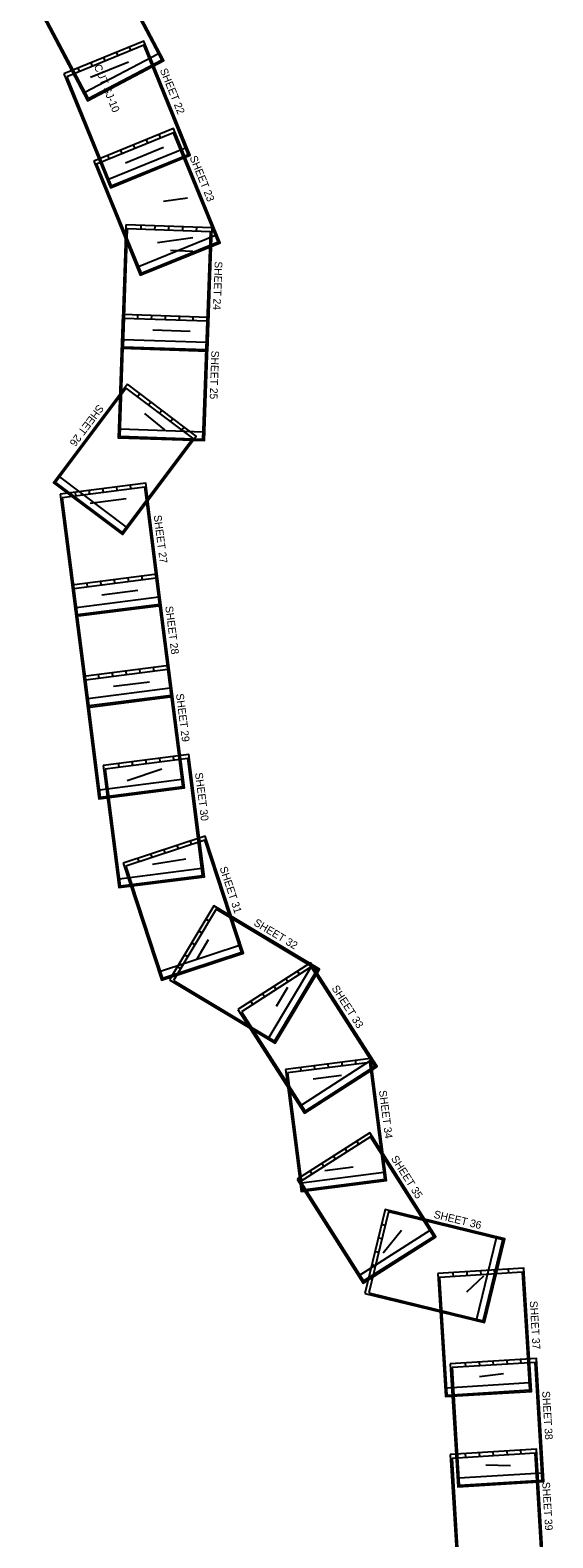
# Model space of a CAD drawing. Extents: x 518852 to 589310, y 1937169 to 2155394.
# Drawn here: x 536569 to 553550, y 2050636 to 2099579 of the extents above; entities that cross this region are included whole.
import ezdxf

# ---------------------------------------------------------------- set-up
doc = ezdxf.new("R2010")
doc.units = 0
doc.layers.add('Level 1', color=7, linetype='Continuous')
doc.layers.add('Level 58', color=7, linetype='Continuous')

msp = doc.modelspace()

# ---------------------------------------------------------------- linework, layer by layer
at = {"layer": 'Level 1'}
for p, q in [((537257, 2099523), (537301, 2099546)), ((540529, 2099214), (540573, 2099237)), ((537467, 2099125), (537511, 2099148)), ((537677, 2098727), (537721, 2098750)), ((540739, 2098815), (538351, 2097556)), ((539011, 2098578), (538963, 2098693)), ((539011, 2098578), (538963, 2098693)), ((539427, 2098747), (539380, 2098863)), ((539427, 2098747), (539380, 2098863)), ((539844, 2098917), (539797, 2099033)), ((539844, 2098917), (539797, 2099033)), ((540431, 2098670), (540477, 2098689)), ((540431, 2098670), (540477, 2098689)), ((537887, 2098329), (537931, 2098352)), ((538177, 2098238), (538130, 2098354)), ((538177, 2098238), (538130, 2098354)), ((538594, 2098408), (538547, 2098523)), ((538594, 2098408), (538547, 2098523)), ((540071, 2098152), (540048, 2098197)), ((540469, 2098362), (540446, 2098407)), ((540600, 2098254), (540647, 2098272)), ((540600, 2098254), (540647, 2098272)), ((538097, 2097931), (538141, 2097954)), ((539275, 2097733), (539252, 2097777)), ((539673, 2097943), (539650, 2097987)), ((540770, 2097837), (540817, 2097856)), ((540770, 2097837), (540817, 2097856)), ((537884, 2097632), (537930, 2097651)), ((537884, 2097632), (537930, 2097651)), ((538054, 2097216), (538100, 2097235)), ((538054, 2097216), (538100, 2097235)), ((538877, 2097523), (538854, 2097567)), ((540940, 2097420), (540986, 2097439)), ((540940, 2097420), (540986, 2097439)), ((538224, 2096799), (538270, 2096818)), ((538224, 2096799), (538270, 2096818)), ((541110, 2097003), (541156, 2097022)), ((541110, 2097003), (541156, 2097022)), ((538394, 2096382), (538440, 2096401)), ((538394, 2096382), (538440, 2096401)), ((541280, 2096587), (541326, 2096606)), ((541280, 2096587), (541326, 2096606)), ((538563, 2095966), (538610, 2095984)), ((538563, 2095966), (538610, 2095984)), ((541619, 2095753), (539119, 2094734)), ((541619, 2095753), (539119, 2094734)), ((539979, 2095738), (539931, 2095854)), ((540395, 2095908), (540348, 2096024)), ((540812, 2096078), (540765, 2096193)), ((541399, 2095831), (541445, 2095850)), ((541450, 2096170), (541496, 2096189)), ((541450, 2096170), (541496, 2096189)), ((538733, 2095549), (538779, 2095568)), ((538733, 2095549), (538779, 2095568)), ((539145, 2095398), (539098, 2095514)), ((539562, 2095568), (539515, 2095684)), ((541307, 2095329), (541288, 2095375)), ((541307, 2095329), (541288, 2095375)), ((541568, 2095414), (541615, 2095433)), ((538852, 2094793), (538898, 2094812)), ((538903, 2095132), (538949, 2095151)), ((538903, 2095132), (538949, 2095151)), ((540056, 2094819), (540038, 2094866)), ((540056, 2094819), (540038, 2094866)), ((540473, 2094989), (540454, 2095035)), ((540473, 2094989), (540454, 2095035)), ((540890, 2095159), (540871, 2095205)), ((540890, 2095159), (540871, 2095205)), ((541738, 2094997), (541785, 2095016)), ((539022, 2094376), (539068, 2094395)), ((539640, 2094649), (539621, 2094696)), ((539640, 2094649), (539621, 2094696)), ((541908, 2094581), (541954, 2094599)), ((539192, 2093959), (539238, 2093978)), ((542078, 2094164), (542124, 2094183)), ((539361, 2093543), (539408, 2093562)), ((542248, 2093747), (542294, 2093766)), ((542418, 2093330), (542464, 2093349)), ((539531, 2093126), (539578, 2093145)), ((542587, 2092914), (540087, 2091895)), ((540175, 2093112), (540180, 2093237)), ((540625, 2093096), (540630, 2093221)), ((541075, 2093081), (541079, 2093206)), ((541525, 2093065), (541529, 2093190)), ((541974, 2093050), (541979, 2093175)), ((539660, 2092679), (539710, 2092677)), ((539701, 2092709), (539747, 2092728)), ((541858, 2092319), (541839, 2092366)), ((542274, 2092489), (542256, 2092535)), ((542409, 2092584), (542459, 2092583)), ((539645, 2092229), (539695, 2092228)), ((539871, 2092293), (539917, 2092311)), ((540608, 2091810), (540589, 2091856)), ((541024, 2091980), (541005, 2092026)), ((541441, 2092150), (541422, 2092196)), ((542393, 2092135), (542443, 2092133)), ((539629, 2091780), (539679, 2091778)), ((542378, 2091685), (542428, 2091683)), ((539598, 2090880), (539648, 2090878)), ((539614, 2091330), (539664, 2091328)), ((542362, 2091235), (542412, 2091233)), ((539583, 2090430), (539633, 2090429)), ((542347, 2090785), (542397, 2090784)), ((539567, 2089981), (539617, 2089979)), ((540067, 2090205), (540071, 2090330)), ((540516, 2090190), (540521, 2090315)), ((540966, 2090174), (540970, 2090299)), ((541416, 2090159), (541420, 2090284)), ((541865, 2090143), (541870, 2090268)), ((542316, 2089886), (542366, 2089884)), ((542331, 2090336), (542381, 2090334)), ((539551, 2089773), (539601, 2089771)), ((542300, 2089436), (539602, 2089529)), ((542300, 2089678), (542350, 2089676)), ((539536, 2089323), (539586, 2089321)), ((540042, 2089239), (540044, 2089289)), ((540492, 2089223), (540493, 2089273)), ((540941, 2089208), (540943, 2089258)), ((541391, 2089192), (541393, 2089242)), ((541841, 2089177), (541843, 2089227)), ((542284, 2089228), (542334, 2089227)), ((539505, 2088424), (539555, 2088422)), ((539520, 2088873), (539570, 2088872)), ((542269, 2088779), (542319, 2088777)), ((539489, 2087974), (539539, 2087972)), ((542253, 2088329), (542303, 2088327)), ((539383, 2087625), (539423, 2087595)), ((539474, 2087524), (539524, 2087522)), ((540053, 2087684), (540128, 2087784)), ((540413, 2087414), (540488, 2087514)), ((542222, 2087429), (542272, 2087428)), ((542238, 2087879), (542288, 2087877)), ((539113, 2087265), (539153, 2087235)), ((539458, 2087074), (539508, 2087073)), ((540773, 2087144), (540848, 2087244)), ((541133, 2086874), (541208, 2086974)), ((542207, 2086980), (542257, 2086978)), ((538573, 2086545), (538613, 2086515)), ((538843, 2086905), (538883, 2086875)), ((542191, 2086530), (539493, 2086623)), ((541493, 2086604), (541568, 2086704)), ((538303, 2086185), (538343, 2086155)), ((539933, 2086333), (539935, 2086383)), ((540383, 2086317), (540385, 2086367)), ((540833, 2086302), (540834, 2086352)), ((541282, 2086286), (541284, 2086336)), ((541583, 2085974), (541623, 2085944)), ((541732, 2086271), (541734, 2086321)), ((538033, 2085825), (538073, 2085795)), ((541312, 2085614), (541352, 2085584)), ((539692, 2083455), (537532, 2085075)), ((537762, 2085465), (537802, 2085435)), ((541042, 2085254), (541082, 2085224)), ((537727, 2084585), (537757, 2084625)), ((538059, 2084458), (538043, 2084582)), ((538505, 2084515), (538489, 2084639)), ((538951, 2084572), (538936, 2084696)), ((539398, 2084629), (539382, 2084753)), ((539844, 2084686), (539828, 2084810)), ((540502, 2084534), (540542, 2084504)), ((540772, 2084894), (540812, 2084864)), ((538087, 2084315), (538117, 2084355)), ((538447, 2084045), (538477, 2084085)), ((540232, 2084174), (540272, 2084144)), ((540348, 2084296), (540397, 2084303)), ((537620, 2083948), (537669, 2083954)), ((538807, 2083775), (538837, 2083815)), ((539167, 2083505), (539197, 2083545)), ((539962, 2083814), (540002, 2083784)), ((540405, 2083850), (540454, 2083856)), ((537677, 2083502), (537726, 2083508)), ((537734, 2083055), (537783, 2083062)), ((540462, 2083404), (540511, 2083410)), ((537791, 2082609), (537840, 2082615)), ((540519, 2082957), (540568, 2082964)), ((537848, 2082162), (537897, 2082169)), ((540576, 2082511), (540625, 2082517)), ((540633, 2082065), (540682, 2082071)), ((537905, 2081716), (537954, 2081722)), ((538432, 2081503), (538417, 2081627)), ((538879, 2081560), (538863, 2081684)), ((539325, 2081617), (539309, 2081741)), ((539772, 2081674), (539756, 2081798)), ((540218, 2081731), (540202, 2081855)), ((540690, 2081618), (540739, 2081625)), ((537962, 2081270), (538012, 2081276)), ((540747, 2081172), (538069, 2080830)), ((540721, 2081342), (540771, 2081348)), ((537993, 2080993), (538043, 2080999)), ((538550, 2080614), (538543, 2080664)), ((538996, 2080671), (538990, 2080721)), ((539442, 2080728), (539436, 2080778)), ((539889, 2080785), (539883, 2080835)), ((540335, 2080842), (540329, 2080892)), ((540778, 2080895), (540828, 2080902)), ((538051, 2080547), (538100, 2080553)), ((538108, 2080100), (538157, 2080107)), ((540835, 2080449), (540885, 2080455)), ((538165, 2079654), (538214, 2079660)), ((540892, 2080003), (540942, 2080009)), ((538222, 2079208), (538271, 2079214)), ((540949, 2079556), (540999, 2079562)), ((541006, 2079110), (541056, 2079116)), ((538279, 2078761), (538328, 2078768)), ((538809, 2078536), (538794, 2078660)), ((539256, 2078593), (539240, 2078717)), ((539702, 2078650), (539686, 2078774)), ((540148, 2078707), (540133, 2078831)), ((540595, 2078764), (540579, 2078888)), ((541064, 2078663), (541113, 2078670)), ((538336, 2078315), (538385, 2078321)), ((541121, 2078217), (538442, 2077875)), ((541098, 2078374), (541148, 2078381)), ((538370, 2078026), (538420, 2078032)), ((538924, 2077659), (538917, 2077709)), ((539370, 2077716), (539364, 2077766)), ((539816, 2077773), (539810, 2077823)), ((540263, 2077830), (540256, 2077880)), ((540709, 2077887), (540703, 2077937)), ((541155, 2077928), (541205, 2077934)), ((538427, 2077580), (538477, 2077586)), ((541212, 2077482), (541262, 2077488)), ((538484, 2077133), (538534, 2077140)), ((538542, 2076687), (538591, 2076693)), ((541269, 2077035), (541319, 2077042)), ((538599, 2076240), (538648, 2076247)), ((541326, 2076589), (541376, 2076595)), ((538656, 2075794), (538705, 2075800)), ((539456, 2075651), (539440, 2075775)), ((539902, 2075708), (539887, 2075832)), ((540349, 2075765), (540333, 2075889)), ((540795, 2075822), (540779, 2075946)), ((541242, 2075879), (541226, 2076003)), ((541383, 2076143), (541433, 2076149)), ((541440, 2075696), (541490, 2075703)), ((538713, 2075348), (538762, 2075354)), ((541497, 2075250), (538819, 2074908)), ((541745, 2075490), (541795, 2075496)), ((539017, 2075141), (539067, 2075147)), ((539074, 2074695), (539124, 2074701)), ((539300, 2074692), (539294, 2074742)), ((539747, 2074749), (539741, 2074799)), ((540193, 2074806), (540187, 2074856)), ((540640, 2074863), (540633, 2074913)), ((541086, 2074920), (541080, 2074970)), ((541802, 2075043), (541852, 2075050)), ((539131, 2074248), (539181, 2074255)), ((541859, 2074597), (541909, 2074603)), ((539188, 2073802), (539238, 2073808)), ((541916, 2074150), (541966, 2074157)), ((539245, 2073356), (539295, 2073362)), ((541816, 2073140), (541777, 2073259)), ((541973, 2073704), (542023, 2073710)), ((542030, 2073258), (542080, 2073264)), ((539302, 2072909), (539352, 2072915)), ((540534, 2072719), (540495, 2072838)), ((540961, 2072860), (540922, 2072978)), ((541389, 2073000), (541350, 2073119)), ((542087, 2072811), (542137, 2072818)), ((542384, 2072853), (542432, 2072869)), ((539359, 2072463), (539409, 2072469)), ((542144, 2072365), (539466, 2072023)), ((540106, 2072579), (540067, 2072698)), ((542525, 2072426), (542572, 2072441)), ((539772, 2071995), (539819, 2072011)), ((539947, 2071807), (539941, 2071857)), ((540394, 2071864), (540387, 2071914)), ((540840, 2071921), (540834, 2071971)), ((541286, 2071978), (541280, 2072028)), ((541733, 2072035), (541726, 2072085)), ((542665, 2071998), (542713, 2072014)), ((539912, 2071568), (539959, 2071584)), ((542805, 2071571), (542853, 2071586)), ((540052, 2071140), (540100, 2071156)), ((542946, 2071143), (542993, 2071159)), ((543002, 2070809), (543028, 2070852)), ((540193, 2070713), (540240, 2070728)), ((540333, 2070285), (540380, 2070301)), ((542154, 2070268), (542047, 2070332)), ((542385, 2070654), (542278, 2070719)), ((543086, 2070715), (543134, 2070731)), ((543226, 2070288), (543274, 2070303)), ((543388, 2070578), (543414, 2070621)), ((543774, 2070347), (543800, 2070390)), ((540473, 2069858), (540521, 2069873)), ((543367, 2069860), (540802, 2069018)), ((541923, 2069882), (541815, 2069946)), ((544160, 2070116), (544186, 2070159)), ((544547, 2069885), (544572, 2069927)), ((540614, 2069430), (540661, 2069446)), ((541691, 2069496), (541584, 2069560)), ((542598, 2069318), (542582, 2069366)), ((543025, 2069459), (543009, 2069506)), ((544933, 2069653), (544958, 2069696)), ((545319, 2069422), (545344, 2069465)), ((541315, 2068897), (541299, 2068945)), ((541460, 2069110), (541353, 2069174)), ((541742, 2069038), (541727, 2069085)), ((542170, 2069178), (542154, 2069225)), ((545705, 2069191), (544318, 2066875)), ((545321, 2068925), (545254, 2069030)), ((541590, 2068450), (541615, 2068493)), ((544565, 2068438), (544497, 2068543)), ((544943, 2068681), (544875, 2068787)), ((545710, 2068664), (545667, 2068689)), ((545943, 2068790), (545985, 2068817)), ((546187, 2068412), (546229, 2068439)), ((541976, 2068219), (542001, 2068262)), ((542362, 2067987), (542387, 2068030)), ((543808, 2067951), (543740, 2068056)), ((544186, 2068194), (544119, 2068299)), ((545247, 2067892), (545204, 2067917)), ((545478, 2068278), (545435, 2068303)), ((546431, 2068034), (546473, 2068061)), ((542748, 2067756), (542773, 2067799)), ((543134, 2067525), (543160, 2067568)), ((545016, 2067505), (544973, 2067531)), ((546674, 2067655), (546716, 2067682)), ((543520, 2067294), (543546, 2067337)), ((543631, 2067302), (543673, 2067329)), ((543875, 2066923), (543917, 2066950)), ((543906, 2067063), (543932, 2067106)), ((544785, 2067119), (544742, 2067145)), ((546918, 2067277), (546960, 2067304)), ((547161, 2066899), (547204, 2066926)), ((544118, 2066545), (544161, 2066572)), ((547405, 2066520), (547447, 2066547)), ((544362, 2066166), (544404, 2066194)), ((545374, 2065783), (545358, 2065907)), ((547649, 2066142), (545379, 2064680)), ((545820, 2065840), (545804, 2065964)), ((546266, 2065898), (546250, 2066021)), ((546713, 2065955), (546697, 2066079)), ((547159, 2066012), (547143, 2066136)), ((544606, 2065788), (544648, 2065815)), ((544849, 2065410), (544891, 2065437)), ((547041, 2065424), (547014, 2065466)), ((547419, 2065667), (547392, 2065709)), ((547663, 2065623), (547712, 2065629)), ((544935, 2065273), (544984, 2065279)), ((545093, 2065031), (545135, 2065059)), ((546284, 2064936), (546257, 2064978)), ((546663, 2065180), (546636, 2065222)), ((547720, 2065177), (547769, 2065183)), ((544992, 2064827), (545042, 2064833)), ((545906, 2064693), (545879, 2064735)), ((547777, 2064730), (547827, 2064737)), ((545049, 2064380), (545099, 2064387)), ((545107, 2063934), (545156, 2063940)), ((547834, 2064284), (547884, 2064290)), ((545164, 2063488), (545213, 2063494)), ((547249, 2063410), (547182, 2063515)), ((547891, 2063838), (547941, 2063844)), ((545221, 2063041), (545271, 2063048)), ((546489, 2062927), (546422, 2063033)), ((546869, 2063168), (546802, 2063274)), ((547870, 2063271), (547912, 2063298)), ((547949, 2063391), (547998, 2063398)), ((545278, 2062595), (545328, 2062601)), ((548063, 2062498), (545385, 2062155)), ((545729, 2062445), (545662, 2062550)), ((546109, 2062686), (546042, 2062792)), ((548006, 2062945), (548056, 2062951)), ((548111, 2062891), (548153, 2062918)), ((548352, 2062511), (548394, 2062538)), ((545866, 2061940), (545860, 2061989)), ((546313, 2061997), (546306, 2062046)), ((546759, 2062054), (546753, 2062104)), ((547206, 2062111), (547199, 2062161)), ((547652, 2062168), (547645, 2062218)), ((548593, 2062131), (548636, 2062158)), ((545548, 2061797), (545591, 2061824)), ((548835, 2061752), (548877, 2061778)), ((545790, 2061417), (545832, 2061444)), ((546031, 2061037), (546073, 2061064)), ((548650, 2061107), (548662, 2061155)), ((549076, 2061372), (549118, 2061398)), ((549087, 2061000), (549099, 2061049)), ((549317, 2060992), (549359, 2061019)), ((546272, 2060657), (546314, 2060684)), ((549558, 2060612), (547279, 2059165)), ((548106, 2060776), (547985, 2060806)), ((549525, 2060893), (549536, 2060942)), ((549962, 2060787), (549974, 2060835)), ((550399, 2060680), (550411, 2060728)), ((550836, 2060573), (550848, 2060622)), ((551273, 2060466), (551285, 2060515)), ((546513, 2060277), (546555, 2060304)), ((548000, 2060339), (547878, 2060369)), ((549326, 2060139), (549299, 2060181)), ((551710, 2060360), (551070, 2057737)), ((546754, 2059897), (546797, 2059924)), ((546996, 2059518), (547038, 2059544)), ((547893, 2059902), (547771, 2059932)), ((548566, 2059656), (548539, 2059698)), ((548946, 2059897), (548919, 2059940)), ((551871, 2059857), (551822, 2059869)), ((547679, 2059028), (547558, 2059058)), ((547786, 2059465), (547665, 2059495)), ((547806, 2059174), (547780, 2059216)), ((548186, 2059415), (548159, 2059457)), ((550319, 2059119), (550312, 2059244)), ((550768, 2059146), (550761, 2059271)), ((551218, 2059174), (551210, 2059299)), ((551667, 2059202), (551659, 2059326)), ((551764, 2059420), (551715, 2059432)), ((552116, 2059229), (552108, 2059354)), ((549848, 2058639), (549898, 2058642)), ((551550, 2058546), (551502, 2058558)), ((551657, 2058983), (551609, 2058995)), ((552593, 2058808), (552643, 2058811)), ((547998, 2058435), (548010, 2058484)), ((548435, 2058329), (548447, 2058377)), ((548872, 2058222), (548884, 2058270)), ((549309, 2058115), (549321, 2058164)), ((549875, 2058190), (549925, 2058193)), ((551444, 2058109), (551395, 2058120)), ((552620, 2058358), (552670, 2058362)), ((549746, 2058008), (549758, 2058057)), ((549903, 2057741), (549953, 2057744)), ((550184, 2057902), (550196, 2057950)), ((550621, 2057795), (550633, 2057843)), ((552648, 2057909), (552698, 2057912)), ((549931, 2057292), (549980, 2057295)), ((552675, 2057460), (552725, 2057463)), ((549958, 2056842), (550008, 2056846)), ((552703, 2057011), (552753, 2057014)), ((549986, 2056393), (550036, 2056396)), ((550725, 2056189), (550717, 2056314)), ((551174, 2056217), (551166, 2056341)), ((551623, 2056244), (551615, 2056369)), ((552072, 2056272), (552064, 2056396)), ((552521, 2056299), (552514, 2056424)), ((552731, 2056562), (552780, 2056565)), ((552758, 2056113), (552808, 2056116)), ((550013, 2055944), (550063, 2055947)), ((552786, 2055664), (550091, 2055498)), ((550253, 2055709), (550303, 2055712)), ((552998, 2055878), (553048, 2055881)), ((550281, 2055260), (550331, 2055263)), ((550557, 2055251), (550554, 2055301)), ((551006, 2055279), (551003, 2055329)), ((551455, 2055306), (551452, 2055356)), ((551904, 2055334), (551901, 2055384)), ((552353, 2055361), (552350, 2055411)), ((553026, 2055429), (553076, 2055432)), ((550308, 2054811), (550358, 2054814)), ((553053, 2054979), (553103, 2054982)), ((550336, 2054362), (550386, 2054365)), ((553081, 2054530), (553131, 2054533)), ((550364, 2053913), (550413, 2053916)), ((553108, 2054081), (553158, 2054084)), ((550391, 2053463), (550441, 2053466)), ((550725, 2053244), (550717, 2053369)), ((551174, 2053271), (551166, 2053396)), ((551623, 2053299), (551615, 2053424)), ((552072, 2053327), (552064, 2053451)), ((552521, 2053354), (552514, 2053479)), ((553136, 2053632), (553186, 2053635)), ((553164, 2053183), (553213, 2053186)), ((550253, 2052764), (550303, 2052767)), ((550419, 2053014), (550469, 2053017)), ((553191, 2052734), (550496, 2052568)), ((552998, 2052933), (553048, 2052936)), ((550281, 2052315), (550331, 2052318)), ((550962, 2052321), (550959, 2052371)), ((551411, 2052349), (551408, 2052399)), ((551860, 2052376), (551857, 2052426)), ((552310, 2052404), (552307, 2052454)), ((552759, 2052432), (552756, 2052481)), ((553026, 2052483), (553076, 2052487)), ((550308, 2051866), (550358, 2051869)), ((553053, 2052034), (553103, 2052037)), ((550336, 2051417), (550386, 2051420)), ((553081, 2051585), (553131, 2051588)), ((550364, 2050967), (550413, 2050971)), ((553108, 2051136), (553158, 2051139)), ((553136, 2050687), (553186, 2050690))]:
    msp.add_line(p, q, dxfattribs=at)
for points in [[(536569, 2100828), (538435, 2097290), (540912, 2098596), (539046, 2102134)], [(536672, 2100741), (538456, 2097357), (540844, 2098616), (539060, 2102000)], [(537667, 2098165), (539177, 2094461), (541770, 2095517), (540260, 2099222)], [(537667, 2098165), (539177, 2094461), (541770, 2095517), (540260, 2099222)], [(537761, 2098068), (539204, 2094526), (541704, 2095545), (540261, 2099087)], [(537761, 2098068), (539204, 2094526), (541704, 2095545), (540261, 2099087)], [(538635, 2095325), (540145, 2091621), (542737, 2092678), (541228, 2096382)], [(538728, 2095228), (540172, 2091686), (542672, 2092705), (541229, 2096247)], [(539680, 2093254), (539542, 2089256), (542341, 2089160), (542478, 2093157)], [(539726, 2093127), (539594, 2089304), (542292, 2089211), (542424, 2093034)], [(539571, 2090347), (539433, 2086350), (542232, 2086253), (542369, 2090251)], [(539617, 2090221), (539485, 2086398), (542183, 2086305), (542315, 2090128)], [(539728, 2088085), (537327, 2084886), (539566, 2083205), (541968, 2086404)], [(539693, 2087955), (537397, 2084895), (539557, 2083275), (541853, 2086334)], [(537547, 2084518), (538054, 2080551), (540831, 2080905), (540324, 2084873)], [(537612, 2084401), (538097, 2080606), (540775, 2080949), (540291, 2084743)], [(537921, 2081563), (538428, 2077596), (541205, 2077951), (540698, 2081918)], [(537986, 2081446), (538471, 2077652), (541149, 2077994), (540664, 2081788)], [(538298, 2078596), (538805, 2074629), (541582, 2074983), (541075, 2078951)], [(538363, 2078479), (538848, 2074684), (541526, 2075027), (541041, 2078821)], [(538944, 2075711), (539451, 2071744), (542229, 2072099), (541722, 2076066)], [(539010, 2075594), (539494, 2071800), (542173, 2072142), (541688, 2075936)], [(539592, 2072542), (540840, 2068741), (543500, 2069615), (542252, 2073415)], [(539679, 2072439), (540872, 2068804), (543437, 2069647), (542244, 2073281)], [(541096, 2068745), (544528, 2066690), (545966, 2069093), (542535, 2071148)], [(541229, 2068724), (544511, 2066759), (545898, 2069076), (542616, 2071040)], [(543320, 2067785), (545486, 2064422), (547840, 2065938), (545674, 2069301)], [(543430, 2067707), (545500, 2064491), (547771, 2065953), (545700, 2069169)], [(544862, 2065843), (545371, 2061876), (548148, 2062232), (547639, 2066200)], [(544927, 2065726), (545414, 2061932), (548092, 2062275), (547605, 2066069)], [(545240, 2062282), (547384, 2058906), (549748, 2060407), (547604, 2063783)], [(545349, 2062204), (547400, 2058975), (549679, 2060422), (547629, 2063651)], [(547439, 2058572), (551325, 2057623), (551989, 2060343), (548104, 2061292)], [(547573, 2058591), (551288, 2057683), (551929, 2060306), (548213, 2061214)], [(549813, 2059213), (550058, 2055221), (552852, 2055392), (552607, 2059385)], [(549870, 2059091), (550105, 2055273), (552799, 2055439), (552565, 2059257)], [(550218, 2056283), (550463, 2052291), (553258, 2052462), (553013, 2056455)], [(550276, 2056161), (550510, 2052344), (553205, 2052509), (552970, 2056327)], [(550218, 2053338), (550463, 2049346), (553258, 2049517), (553013, 2053510)], [(550276, 2053216), (550510, 2049398), (553205, 2049564), (552970, 2053382)]]:
    msp.add_lwpolyline(points, close=True, dxfattribs=at)
at = {"layer": 'Level 58'}
for p, q in [((538535, 2098055), (539766, 2098556)), ((539667, 2095276), (540898, 2095778)), ((540902, 2094028), (541677, 2094137)), ((540705, 2092688), (541858, 2092850)), ((541126, 2092433), (541859, 2092408)), ((540558, 2089851), (541769, 2089810)), ((540941, 2086600), (540296, 2087133)), ((538514, 2084229), (539689, 2084380)), ((538894, 2081253), (540070, 2081404)), ((539274, 2078278), (540450, 2078428)), ((539723, 2075225), (540849, 2075605)), ((540545, 2072506), (541626, 2072680)), ((541994, 2069432), (542368, 2070056)), ((544568, 2067891), (544942, 2068515)), ((545758, 2065536), (546680, 2065654)), ((546140, 2062560), (547062, 2062678)), ((548033, 2059885), (548633, 2060619)), ((550760, 2058624), (551310, 2059138)), ((551163, 2055873), (551951, 2055974)), ((551369, 2053008), (552170, 2052983))]:
    msp.add_line(p, q, dxfattribs=at)

# ---------------------------------------------------------------- texts
for s, rotation, p in [('CUT SJ-10', 292.2508, (538634, 2098413)), ('SHEET 22', 292.173, (540777, 2098284)), ('SHEET 23', 292.173, (541744, 2095446)), ('SHEET 24', 268.0259, (542566, 2092078)), ('SHEET 25', 268.0259, (542458, 2089179)), ('SHEET 26', 233.107, (538783, 2087449)), ('SHEET 27', 277.2812, (540584, 2083824)), ('SHEET 28', 277.2812, (540958, 2080870)), ('SHEET 29', 277.2812, (541307, 2078028)), ('SHEET 30', 277.2812, (541924, 2075463)), ('SHEET 31', 288.1741, (542722, 2072385)), ('SHEET 32', 329.0899, (543810, 2070538)), ('SHEET 33', 302.7794, (546353, 2068477)), ('SHEET 34', 277.3084, (547900, 2065150)), ('SHEET 35', 302.4165, (548281, 2062950)), ('SHEET 36', 346.2767, (549662, 2061030)), ('SHEET 37', 273.5139, (552798, 2058322)), ('SHEET 38', 273.5139, (553203, 2055393)), ('SHEET 39', 273.5139, (553203, 2052445))]:
    msp.add_text(s, height=250, rotation=rotation, dxfattribs=at).set_placement(p)

doc.saveas('drawing.dxf')
